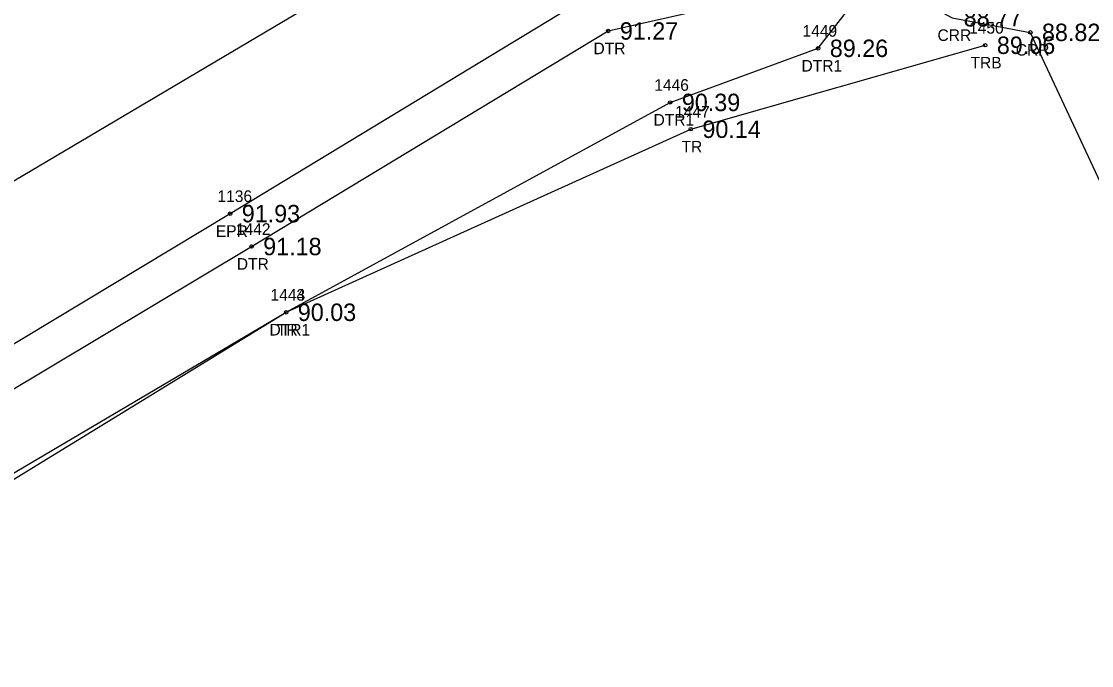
# Model space of a CAD drawing. Extents: x 2529517 to 2532038, y 935000 to 936944.
# Drawn here: x 2531034.4 to 2531126.5, y 935866 to 935921.4 of the extents above; entities that cross this region are included whole.
import ezdxf

# ---------------------------------------------------------------- set-up
doc = ezdxf.new("R2010")
doc.units = 0
for name, color, linetype in [('Default', 7, 'Continuous'), ('RD_EX_H2O', 7, 'Continuous'), ('RD_EX_H2O_txCode', 7, 'Continuous'), ('RD_EX_Road', 7, 'Continuous'), ('RD_EX_Road_txCode', 7, 'Continuous'), ('RD_EX_TX_H2O_ELEV', 7, 'Continuous'), ('RD_EX_TX_Road_ELEV', 7, 'Continuous'), ('RD_EX_TX_VEG_ELEV', 7, 'Continuous'), ('RD_EX_VEG', 7, 'Continuous'), ('RD_EX_VEG_txCode', 7, 'Continuous'), ('RD_HC_Cl', 7, 'Continuous'), ('RD_SMD_Locator', 7, 'Continuous')]:
    doc.layers.add(name, color=color, linetype=linetype)

msp = doc.modelspace()

# ---------------------------------------------------------------- linework, layer by layer
at = {"layer": 'Default'}
msp.add_line((2530557.048, 935625.341), (2531768.068, 936342.554), dxfattribs=at)
at = {"layer": 'RD_EX_H2O'}
for points in [[(2531078.875, 935952.281), (2531078.96, 935951.177), (2531094.183, 935926.972), (2531103.295, 935929.494), (2531106.667, 935929.665), (2531109.751, 935927.847), (2531109.937, 935928.671), (2531111.529, 935928.19), (2531109.984, 935924.149), (2531114.473, 935921.713), (2531121.2, 935920.45), (2531134.651, 935891.599), (2531155.43, 935754.455), (2531173.735, 935652.906), (2531186.187, 935572.514), (2531201.43, 935446.699)], [(2531014.512, 935871.147), (2531011.198, 935876.261), (2531054.239, 935902.022), (2531084.907, 935920.574), (2531098.798, 935923.754), (2531103.295, 935929.494)], [(2531014.512, 935871.147), (2531057.214, 935896.364), (2531090.236, 935914.424), (2531102.959, 935919.079), (2531109.751, 935927.847)]]:
    msp.add_lwpolyline(points, dxfattribs=at)
at = {"layer": 'RD_EX_Road'}
msp.add_lwpolyline([(2530212.444, 935579.718), (2530312.608, 935580.142), (2530402.982, 935580.636), (2530451.057, 935579.535), (2530466.913, 935580.348), (2530487.453, 935583.291), (2530533.43, 935598.455), (2530580.282, 935625.084), (2530621.694, 935649.225), (2530704.615, 935698.354), (2530718.668, 935706.376), (2530795.45, 935752.358), (2530871.328, 935796.67), (2530882.405, 935803.04), (2530947.168, 935842.26), (2530966.001, 935852.419), (2530992.723, 935868.002), (2531009.487, 935879.014), (2531052.394, 935904.854), (2531090.884, 935928.231)], dxfattribs=at)
at = {"layer": 'RD_EX_VEG'}
msp.add_lwpolyline([(2531043.31, 935749.464), (2531037.626, 935787.205), (2531059.819, 935809.298), (2531081.939, 935810.853), (2531064.791, 935856.974), (2531020.066, 935864.933), (2531018.248, 935872.471), (2531057.214, 935896.364), (2531092.005, 935912.116), (2531117.324, 935919.344)], dxfattribs=at)
at = {"layer": 'RD_HC_Cl'}
msp.add_line((2530557.048, 935625.341), (2531768.068, 936342.554), dxfattribs=at)
at = {"layer": 'RD_SMD_Locator'}
for centre in [(2531084.907, 935920.574), (2531121.2, 935920.45), (2531102.959, 935919.079), (2531117.324, 935919.344), (2531090.236, 935914.424), (2531092.005, 935912.116), (2531052.394, 935904.854), (2531054.239, 935902.022), (2531057.214, 935896.364), (2531057.214, 935896.364)]:
    msp.add_circle(centre, 0.15, dxfattribs=at)

# ---------------------------------------------------------------- texts
at = {"layer": 'RD_EX_H2O_txCode'}
for s, p in [('1449', (2531101.613, 935920.079)), ('CRR', (2531113.221, 935919.713)), ('DTR', (2531083.639, 935918.574)), ('CRR', (2531119.948, 935918.45)), ('DTR1', (2531101.526, 935917.079)), ('1446', (2531088.866, 935915.424)), ('DTR1', (2531088.803, 935912.424)), ('1442', (2531052.893, 935903.022)), ('DTR', (2531052.971, 935900.022)), ('1443', (2531055.868, 935897.364)), ('DTR1', (2531055.781, 935894.364))]:
    msp.add_text(s, height=1, dxfattribs=at).set_placement(p)
at = {"layer": 'RD_EX_Road_txCode'}
for s, p in [('1136', (2531051.307, 935905.854)), ('EPR', (2531051.165, 935902.854))]:
    msp.add_text(s, height=1, dxfattribs=at).set_placement(p)
at = {"layer": 'RD_EX_TX_H2O_ELEV'}
for s, p in [('88.77', (2531115.473, 935920.963)), ('91.27', (2531085.907, 935919.824)), ('88.82', (2531122.2, 935919.7)), ('89.26', (2531103.959, 935918.329)), ('90.39', (2531091.236, 935913.674)), ('91.18', (2531055.239, 935901.272)), ('90.03', (2531058.214, 935895.614))]:
    msp.add_text(s, height=1.5, dxfattribs=at).set_placement(p)
at = {"layer": 'RD_EX_TX_Road_ELEV'}
msp.add_text('91.93', height=1.5, dxfattribs=at).set_placement((2531053.394, 935904.104))
at = {"layer": 'RD_EX_TX_VEG_ELEV'}
for s, p in [('89.06', (2531118.324, 935918.594)), ('90.14', (2531093.005, 935911.366)), ('90.03', (2531058.214, 935895.614))]:
    msp.add_text(s, height=1.5, dxfattribs=at).set_placement(p)
at = {"layer": 'RD_EX_VEG_txCode'}
for s, p in [('1450', (2531115.938, 935920.344)), ('TRB', (2531116.056, 935917.344)), ('1447', (2531090.659, 935913.116)), ('TR', (2531091.21, 935910.116)), ('1444', (2531055.868, 935897.364)), ('TR', (2531056.419, 935894.364))]:
    msp.add_text(s, height=1, dxfattribs=at).set_placement(p)

doc.saveas('drawing.dxf')
